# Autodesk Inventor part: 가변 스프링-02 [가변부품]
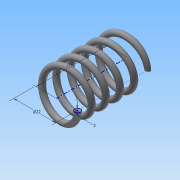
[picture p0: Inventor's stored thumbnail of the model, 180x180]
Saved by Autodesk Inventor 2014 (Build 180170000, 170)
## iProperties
Created: 2015-09
Part Number: 가변 스프링-02 [가변부품]
Material: 강철, 탄소
Document SubType Name: Modeling
Designer: study
Density: 7.87 g/cm^3
Appearance: 반연마
Mass: 18.9156 g
Surface Area: 32.5757 cm^2
Volume: 2.40351 cm^3
Author: study
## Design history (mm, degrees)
sketch "스케치1"
  geometry: L1 (0, 0)-(11, 0); L2 (11, 0)-(11, 39.945); L3 (11, 39.945)-(0, 39.945); L4 (0, 39.945)-(0, 0); C1 r 1.5 at (11, 0)
  constraints: 8 end point, 2 parallel, 1 centre point, 1 coincident, 1 horizontal, 1 perpendicular
  dimensions: "d0" = 39.9455 distance of L3.end L1.start (derived); "d1" = 22 diameter of L2 L4; "d2" = 3 diameter of C1
feature "코일1" sketch "스케치1" pitch "d3" = 10; turns "d5" = 5; dims "d4" = 39.9455 (= d0), "d6" = 0, angle "d7" = 90 deg, angle "d8" = 90 deg, "d9" = 0, "d10" = 0
sketch "스케치2"
  geometry: L1 (-12.5, 0)-(-9.5, 0) reference; 1 further point
  constraints: 1 horizontal alignment
extrude "돌출1" cut sketch "스케치2" distance "d11" = 10; taper "d12" = 0 deg
node "작업 평면1"
sketch "스케치3"
  geometry: L1 (-9.5, 0)-(-12.5, 0) reference; 1 further point
  constraints: 1 horizontal alignment
extrude "돌출2" cut sketch "스케치3" distance "d14" = 10; taper "d15" = 0 deg
node "솔리드1"
node "절단 모서리 투영1"
node "절단 모서리 투영2"
other parameters: "d13" = 39.9455 (= d0)
